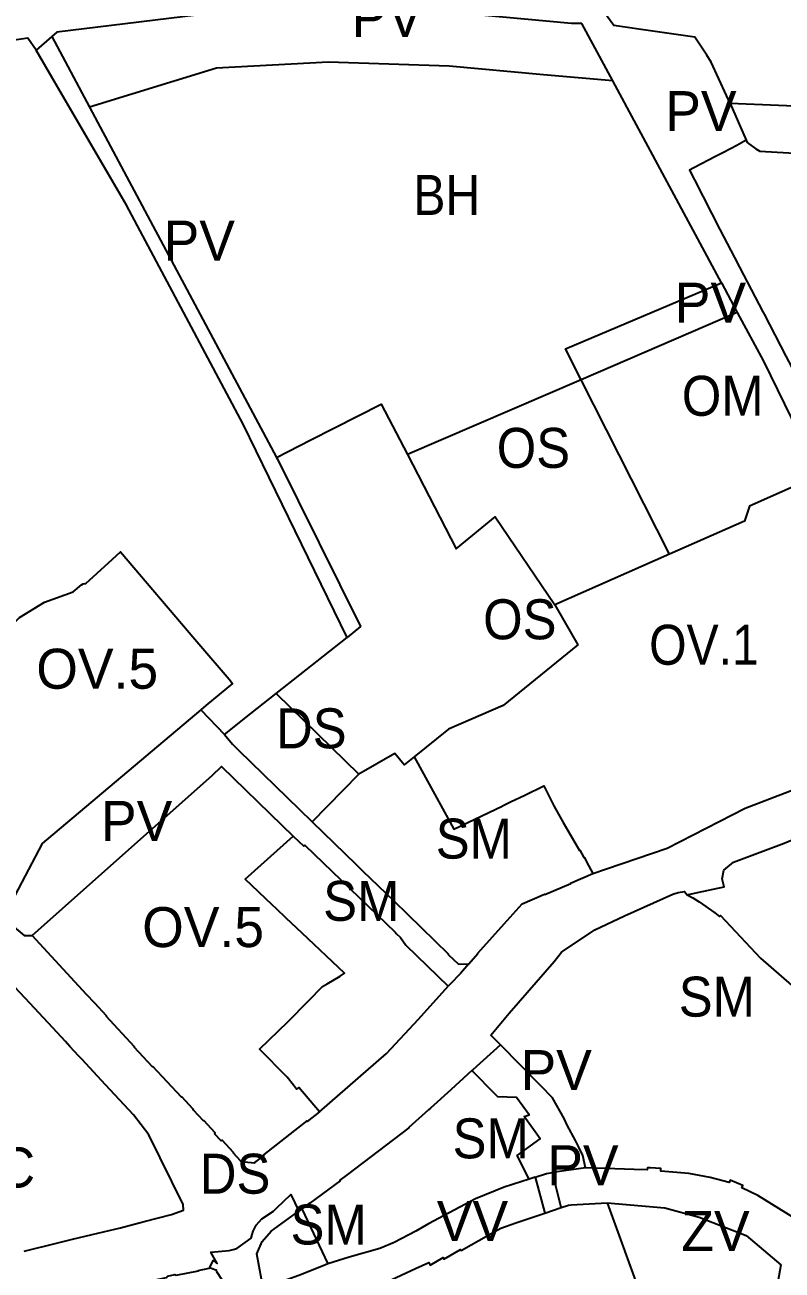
# Model space of a CAD drawing. Extents: x -650451 to -642268, y -1075216 to -1066610.
# Drawn here: x -647437.7 to -647153.7, y -1070308.6 to -1069841.6 of the extents above; entities that cross this region are included whole.
import ezdxf

# ---------------------------------------------------------------- set-up
doc = ezdxf.new("R2010")
doc.units = 0
doc.header["$LTSCALE"] = 6
doc.layers.add('1', color=7, linetype='Continuous', lineweight=35)
doc.layers.add('2', color=7, linetype='Continuous')
doc.layers.add('3', color=7, linetype='Continuous')

msp = doc.modelspace()

# ---------------------------------------------------------------- linework, layer by layer
at = {"layer": '1'}
for p, q in [((-647217.177, -1069862.57), (-647228.77, -1069840.98)), ((-647427.62, -1069845.94), (-647433.48, -1069851.02)), ((-647427.62, -1069845.94), (-647413.462, -1069872.442)), ((-647176.499, -1069938.333), (-647217.177, -1069862.57)), ((-647173.23, -1069871.09), (-647167.14, -1069884.85)), ((-647413.462, -1069872.442), (-647343.28, -1070003.81)), ((-647176.499, -1069938.333), (-647170.546, -1069949.42)), ((-647170.546, -1069949.42), (-647229.096, -1069974.658)), ((-647229.096, -1069974.658), (-647294.257, -1070002.745)), ((-647195.933, -1070040.107), (-647238.99, -1070059.05)), ((-647343.454, -1070092.368), (-647316.82, -1070071.35)), ((-647343.454, -1070092.368), (-647312.485, -1070122.583)), ((-647371.716, -1070098.46), (-647362.87, -1070107.74)), ((-647329.932, -1070140.465), (-647312.485, -1070122.583)), ((-647227.49, -1070270.31), (-647239.781, -1070272.031)), ((-647236.567, -1070285.154), (-647239.781, -1070272.031)), ((-647246.28, -1070273.733), (-647248.56, -1070274.48)), ((-647246.28, -1070273.733), (-647242.698, -1070287.238)), ((-647333.87, -1070285.66), (-647334.91, -1070286.51)), ((-647333.87, -1070285.66), (-647324.11, -1070306.21)), ((-647242.698, -1070287.238), (-647236.567, -1070285.154)), ((-647219.36, -1070283.36), (-647199.79, -1070337.21))]:
    msp.add_line(p, q, dxfattribs=at)
for points in [[(-647173.23, -1069871.09), (-647174.58, -1069868.03), (-647180.29, -1069855.47), (-647181.99, -1069852.94), (-647186.43, -1069846.14), (-647206.6, -1069843.28), (-647216.82, -1069841.82), (-647228.12, -1069826.33)], [(-647228.77, -1069840.98), (-647232.66, -1069841.07), (-647266.62, -1069837.86), (-647270.71, -1069837.61), (-647285.9, -1069836.66), (-647326.71, -1069835.46), (-647363.21, -1069836.64), (-647425.73, -1069844.31), (-647427.62, -1069845.94)], [(-647433.48, -1069851.02), (-647436.61, -1069846.52), (-647487.26, -1069854), (-647497.78, -1069855.56), (-647555.79, -1069863.4), (-647557.18, -1069863.59), (-647579.04, -1069866.8)], [(-647316.82, -1070071.35), (-647355.89, -1069991.27), (-647399.62, -1069909.23), (-647428.49, -1069859.62), (-647433.48, -1069851.02)], [(-647217.177, -1069862.57), (-647243.231, -1069860.34), (-647278.525, -1069857.002), (-647323.794, -1069855.468), (-647365.866, -1069857.774), (-647413.462, -1069872.442)], [(-646931.67, -1069902.89), (-646964.111, -1069878.315), (-647034.195, -1069877.629), (-647076, -1069875.85), (-647081.25, -1069875.56), (-647081.26, -1069875.76), (-647088.94, -1069875.34), (-647088.93, -1069875.14), (-647094.24, -1069874.85), (-647116.31, -1069873.65), (-647118.77, -1069873.51), (-647133.58, -1069872.73), (-647136.94, -1069872.55), (-647173.23, -1069871.09)], [(-647167.14, -1069884.85), (-647170.7, -1069886.73), (-647173.11, -1069888.06), (-647175.97, -1069889.5), (-647178.65, -1069890.92), (-647181.28, -1069892.3), (-647183.94, -1069893.7), (-647186.76, -1069895.19), (-647188.44, -1069896.08), (-647186.59, -1069899.62), (-647177.05, -1069918.33), (-647171.55, -1069928.83), (-647169.72, -1069932.48), (-647160.94, -1069949.14), (-647160.47, -1069950.02), (-647152.31, -1069965.78), (-647150.08, -1069970.1), (-647143.26, -1069983.28), (-647133.1, -1070003.01), (-647125.2, -1070018.46)], [(-647167.14, -1069884.85), (-647166.8, -1069885.63), (-647163.55, -1069887.98), (-647162.03, -1069888.89), (-647111.76, -1069891.77), (-647075.97, -1069894.33), (-647071, -1069897.87), (-647068.2, -1069902.28)], [(-647229.096, -1069974.658), (-647235, -1069963), (-647176.499, -1069938.333)], [(-647170.546, -1069949.42), (-647160.71, -1069967.74), (-647139.86, -1070010.451)], [(-647139.86, -1070010.451), (-647141.46, -1070011.19), (-647165.92, -1070022.1), (-647167.8, -1070027.73), (-647195.933, -1070040.107), (-647229.096, -1069974.658)], [(-647343.28, -1070003.81), (-647330.5, -1069997.19), (-647304.05, -1069983.79), (-647294.257, -1070002.745)], [(-647343.28, -1070003.81), (-647342.93, -1070004.49), (-647311.89, -1070067.23), (-647316.82, -1070071.35)], [(-647294.257, -1070002.745), (-647276, -1070038.08), (-647261.27, -1070026.12), (-647238.99, -1070059.05)], [(-647494.48, -1070118.97), (-647475.14, -1070102.26), (-647469.98, -1070097.81), (-647465.52, -1070093.96), (-647466.24, -1070093.1), (-647458.51, -1070086.65), (-647452.9, -1070076.57), (-647452.1, -1070075.79), (-647446.62, -1070070.42), (-647439.74, -1070063.82), (-647430.34, -1070058.11), (-647419.58, -1070054.2), (-647416.4, -1070051.55), (-647415.86, -1070051.26), (-647415.07, -1070051.09), (-647414.82, -1070051.12), (-647406.39, -1070043.34), (-647401.88, -1070039.17), (-647373.94, -1070071.97), (-647372.43, -1070073.74), (-647361.13, -1070087.01), (-647359.79, -1070088.58), (-647369.83, -1070096.87), (-647371.716, -1070098.46)], [(-647238.99, -1070059.05), (-647230.37, -1070074.09), (-647258.36, -1070096.89), (-647278.81, -1070105.73), (-647291.67, -1070116.04)], [(-647362.87, -1070107.74), (-647352.96, -1070099.87), (-647343.454, -1070092.368)], [(-647371.716, -1070098.46), (-647431.15, -1070148.56), (-647441.5, -1070168.07), (-647445.26, -1070171.55)], [(-647224.72, -1070159.87), (-647219.58, -1070158.11), (-647196.84, -1070150.3), (-647167.62, -1070135.33), (-647134.29, -1070122.54), (-647109.06, -1070114.67), (-647093.03, -1070110.71), (-647094.36, -1070102.91)], [(-647362.87, -1070107.74), (-647359.8, -1070111.34), (-647357.4, -1070113.69), (-647334.81, -1070135.73), (-647329.932, -1070140.465)], [(-647291.67, -1070116.04), (-647295.47, -1070119.09), (-647298.91, -1070114.8), (-647312.485, -1070122.583)], [(-647291.67, -1070116.04), (-647276.77, -1070143.22), (-647258.67, -1070134.54), (-647258.53, -1070134.47), (-647255.52, -1070133), (-647250.23, -1070130.43), (-647243.13, -1070126.97), (-647239.33, -1070134.48), (-647236.92, -1070138.78), (-647235.82, -1070140.75), (-647229.75, -1070151.22), (-647229.53, -1070151.08), (-647228.02, -1070153.9), (-647227.88, -1070153.85), (-647227.04, -1070155.44), (-647224.72, -1070159.87)], [(-647434.91, -1070183.16), (-647412.16, -1070162.89), (-647367.48, -1070123.07), (-647363.9, -1070119.75), (-647341.29, -1070141.7), (-647337.02, -1070145.84)], [(-647329.932, -1070140.465), (-647313.59, -1070156.33), (-647311.04, -1070158.81), (-647299.35, -1070170.16), (-647278.8, -1070190.09), (-647278.9, -1070190.2), (-647275.12, -1070193.84), (-647271.26, -1070193.8)], [(-647189.3, -1070167.85), (-647185.48, -1070167.02), (-647175.42, -1070164.82), (-647176.2, -1070161.88), (-647175.57, -1070158.57), (-647171.94, -1070155.64), (-647153, -1070148.46), (-647136.65, -1070141.75)], [(-647327.26, -1070249.3), (-647335.01, -1070240.09), (-647335.77, -1070240.77), (-647336.97, -1070239.27), (-647339.28, -1070236.31), (-647349.72, -1070225.74), (-647339.1, -1070215.49), (-647331.39, -1070207.67), (-647326.02, -1070202.22), (-647324.35, -1070201.23), (-647319.45, -1070198.33), (-647317.85, -1070197.29), (-647333.74, -1070182.2), (-647339.69, -1070176.56), (-647343.38, -1070173.05), (-647344.91, -1070171.59), (-647355.06, -1070161.92), (-647337.02, -1070145.84)], [(-647337.02, -1070145.84), (-647333.14, -1070149.61), (-647332.76, -1070149.21), (-647298.86, -1070181.89), (-647298.41, -1070182.33), (-647296.79, -1070183.9), (-647294.81, -1070186.79), (-647278.96, -1070202.16)], [(-647271.26, -1070193.8), (-647267.77, -1070189.88), (-647267.88, -1070189.78), (-647257.97, -1070178.72), (-647251.26, -1070171.18), (-647242.77, -1070167.55), (-647242.69, -1070167.74), (-647232.99, -1070163.62), (-647233.07, -1070163.43), (-647224.72, -1070159.87)], [(-647259.35, -1070224.18), (-647262.94, -1070220.53), (-647256.07, -1070212.25), (-647239.24, -1070192.85), (-647236.4, -1070189.4), (-647223.97, -1070180.95), (-647212.77, -1070175.69), (-647194.68, -1070167.58), (-647192.66, -1070167.03), (-647190.29, -1070166.55), (-647189.3, -1070167.85)], [(-647189.3, -1070167.85), (-647187.19, -1070168.95), (-647184.81, -1070170.44), (-647178.9, -1070174.56), (-647177.2, -1070175.96), (-647176.8, -1070175.6), (-647161.79, -1070191.62), (-647150.22, -1070201.78), (-647137.83, -1070209.38), (-647133.27, -1070212.02), (-647133, -1070212.16), (-647128.24, -1070215.02), (-647128.12, -1070215.02), (-647127.89, -1070215.01), (-647117.77, -1070219.6), (-647118.41, -1070220.95), (-647111.9, -1070224.83), (-647098.01, -1070229.05)], [(-647445.26, -1070171.55), (-647447.72, -1070175.08), (-647438, -1070183.09), (-647434.91, -1070183.16)], [(-647327.26, -1070249.3), (-647331.78, -1070252.83), (-647331.91, -1070252.67), (-647348.25, -1070265.44), (-647348.13, -1070265.59), (-647351.52, -1070268.23), (-647351.56, -1070268.45), (-647356.58, -1070268.06), (-647356.65, -1070267.77), (-647359.57, -1070264.62), (-647359.42, -1070264.47), (-647363.71, -1070259.92), (-647363.84, -1070260.04), (-647364.14, -1070260.16), (-647366.57, -1070257.54), (-647366.32, -1070257.08), (-647370.55, -1070252.52), (-647370.7, -1070252.66), (-647374.49, -1070248.61), (-647374.55, -1070248.25), (-647378.81, -1070243.67), (-647378.96, -1070243.8), (-647389.67, -1070232.27), (-647389.81, -1070232.41), (-647396.68, -1070224.96), (-647396.53, -1070224.82), (-647407.25, -1070213.35), (-647407.11, -1070213.21), (-647411.42, -1070208.52), (-647414.54, -1070205.26), (-647434.91, -1070183.16)], [(-647271.26, -1070193.8), (-647274.38, -1070197.37), (-647278.23, -1070201.38), (-647278.96, -1070202.16)], [(-647437.93, -1070301.54), (-647433.43, -1070300.43), (-647430.34, -1070299.66), (-647419.84, -1070297.07), (-647412.48, -1070295.21), (-647401.84, -1070292.82), (-647392.92, -1070290.41), (-647382.67, -1070287.78), (-647378.17, -1070286.15), (-647378.35, -1070284.02), (-647391.25, -1070257.93), (-647396.97, -1070250.36), (-647407.45, -1070239.08), (-647416.38, -1070229.45), (-647417.42, -1070228.34), (-647420.78, -1070224.72), (-647422.49, -1070222.88), (-647427.26, -1070217.79), (-647437.57, -1070206.6), (-647443.43, -1070200.35)], [(-647327.26, -1070249.3), (-647302.11, -1070227.4), (-647290.12, -1070214.47), (-647278.96, -1070202.16)], [(-647259.35, -1070224.18), (-647269.65, -1070233.45), (-647270.03, -1070233.79)], [(-647227.49, -1070270.31), (-647228.49, -1070265.6), (-647229.92, -1070262.5), (-647231.2, -1070260), (-647234.29, -1070254.23), (-647235.44, -1070251.71), (-647239.84, -1070243.95), (-647244.22, -1070239.51), (-647259.35, -1070224.18)], [(-647270.03, -1070233.79), (-647274.88, -1070238.11), (-647276.17, -1070239.32), (-647278, -1070241.03), (-647285.62, -1070247.84), (-647286.37, -1070248.5), (-647293.74, -1070255.11), (-647293.66, -1070255.2), (-647316.66, -1070272.74), (-647319.59, -1070274.94), (-647319.49, -1070275.08), (-647330.78, -1070283.55), (-647330.88, -1070283.41), (-647333.87, -1070285.66)], [(-647248.56, -1070274.48), (-647253.03, -1070265.67), (-647244.42, -1070259.35), (-647250.5, -1070251), (-647248.62, -1070250.39), (-647253.28, -1070243.85), (-647260.36, -1070243.59), (-647260.91, -1070243.03), (-647270.03, -1070233.79)], [(-647246.28, -1070273.733), (-647242.06, -1070272.35), (-647239.781, -1070272.031)], [(-647149.71, -1070288.72), (-647162.8, -1070280.61), (-647168.79, -1070277.75), (-647168.5, -1070276.87), (-647173.22, -1070274.93), (-647173.54, -1070275.79), (-647180.68, -1070273.87), (-647188.74, -1070272.36), (-647199.19, -1070271.47), (-647199.14, -1070270.57), (-647203.16, -1070270.29), (-647204.22, -1070270.22), (-647204.27, -1070271.05), (-647209.25, -1070270.93), (-647227.49, -1070270.31)], [(-647248.56, -1070274.48), (-647258, -1070277.57), (-647268.68, -1070281.94), (-647286.27, -1070291.31), (-647291.02, -1070294.03), (-647299.21, -1070298.24), (-647304.56, -1070300.5), (-647316.11, -1070303.79), (-647324.11, -1070306.21)], [(-647368.29, -1070307.63), (-647367.038, -1070305.027), (-647366.9, -1070305.07), (-647365.59, -1070306.17), (-647368.02, -1070301.95), (-647361.04, -1070301.21), (-647359.59, -1070300.92), (-647358.15, -1070300.54), (-647352.83, -1070296.62), (-647352.48, -1070295.25), (-647352.07, -1070294.06), (-647350.9, -1070291.81), (-647348.88, -1070289.42), (-647344.5, -1070286.5), (-647343.35, -1070285.4), (-647337.99, -1070280.29), (-647334.91, -1070286.51)], [(-647346.97, -1070315.05), (-647349, -1070312), (-647350.67, -1070302.55), (-647348.677, -1070297.894), (-647345.27, -1070293.99), (-647343.9, -1070292.96), (-647337.56, -1070288.43), (-647336.22, -1070287.43), (-647334.91, -1070286.51)], [(-647236.567, -1070285.154), (-647233.82, -1070284.22), (-647232.87, -1070284.15), (-647219.36, -1070283.36)], [(-647219.36, -1070283.36), (-647197.68, -1070285.3), (-647184.77, -1070288.73), (-647167.15, -1070295.69), (-647154.23, -1070306.63), (-647155.89, -1070316.51), (-647167.43, -1070322.66), (-647189.63, -1070330.53), (-647199.79, -1070337.21)], [(-647336.3, -1070330.36), (-647325.69, -1070324.05), (-647303.74, -1070313.73), (-647302.03, -1070312.86), (-647301.91, -1070313.05), (-647291.17, -1070307.98), (-647286.23, -1070305.72), (-647285.69, -1070306.76), (-647280.83, -1070303.93), (-647280.52, -1070304.49), (-647274.32, -1070300.9), (-647274.12, -1070301.25), (-647263.72, -1070295.43), (-647259.22, -1070292.91), (-647253.53, -1070290.92), (-647242.698, -1070287.238)], [(-647511.56, -1070388.55), (-647510.32, -1070387.55), (-647494.55, -1070375.98), (-647486.03, -1070369.57), (-647477.41, -1070363.13), (-647459.55, -1070349.9), (-647451.74, -1070344), (-647451.79, -1070343.93), (-647443.87, -1070337.99), (-647443.82, -1070338.05), (-647435.8, -1070332.03), (-647423.3, -1070324.62), (-647409.73, -1070316.55), (-647397.07, -1070313.99), (-647384.62, -1070311.34), (-647384.21, -1070310.93), (-647381.52, -1070310.31), (-647380.93, -1070310.53), (-647372.64, -1070308.89), (-647372.66, -1070308.81), (-647368.62, -1070307.94), (-647368.36, -1070307.73), (-647368.29, -1070307.63)], [(-647368.29, -1070307.63), (-647365.89, -1070308.63), (-647365.91, -1070308.69), (-647365.84, -1070309.08), (-647363.7, -1070312.42), (-647363.62, -1070312.37), (-647360.6, -1070316.63), (-647360.66, -1070316.67), (-647358.16, -1070320.24), (-647357.84, -1070320.39), (-647357.73, -1070320.44), (-647357.93, -1070321.13), (-647357.43, -1070321.85)], [(-647324.11, -1070306.21), (-647324.94, -1070306.63), (-647333.97, -1070310.22), (-647346.97, -1070315.05)]]:
    msp.add_lwpolyline(points, dxfattribs=at)

# ---------------------------------------------------------------- texts
at = {"layer": '2'}
for s, p in [('PV', (-647197.556, -1069881.391)), ('PV', (-647385.663, -1069929.97)), ('OV.5', (-647433.41, -1070090.55)), ('PV', (-647409.158, -1070147.603)), ('OV.5', (-647393.7, -1070187.46)), ('PV', (-647251.819, -1070241.088)), ('VV', (-647283.206, -1070297.736))]:
    msp.add_text(s, height=15, dxfattribs=at).set_placement(p)
for s, width, p in [('OM', 0.95, (-647191.33, -1069988.17)), ('OS', 0.95, (-647265.844, -1070072.008)), ('OV.1', 0.9, (-647203.58, -1070081.55)), ('SM', 0.95, (-647283.604, -1070154.273)), ('SM', 0.95, (-647325.834, -1070177.611)), ('SM', 0.95, (-647192.476, -1070213.543)), ('SM', 0.95, (-647277.299, -1070266.704)), ('SC', 0.95, (-647460.358, -1070277.603)), ('DS', 0.95, (-647372.099, -1070279.961))]:
    msp.add_text(s, height=15, dxfattribs=dict(at, width=width)).set_placement(p)
at = {"layer": '3'}
for s, p in [('PV', (-647315.168, -1069846.092)), ('PV', (-647193.966, -1069953.25)), ('PV', (-647241.787, -1070276.819)), ('ZV', (-647191.512, -1070301.467))]:
    msp.add_text(s, height=15, dxfattribs=at).set_placement(p)
for s, width, p in [('BH', 0.9, (-647292.016, -1069912.847)), ('OS', 0.95, (-647260.75, -1070007.716)), ('DS', 0.95, (-647343.505, -1070112.898)), ('SM', 0.95, (-647338.079, -1070299.016))]:
    msp.add_text(s, height=15, dxfattribs=dict(at, width=width)).set_placement(p)

doc.saveas('drawing.dxf')
